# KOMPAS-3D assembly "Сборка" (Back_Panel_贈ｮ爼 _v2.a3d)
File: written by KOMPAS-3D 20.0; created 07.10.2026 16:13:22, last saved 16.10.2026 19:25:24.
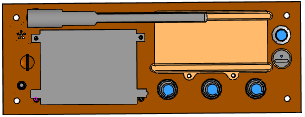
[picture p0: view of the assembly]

Document properties: Полное имя файла: D:\myProjects\Progect_esp32\box_compas\сборки компонентов\Back_Panel_Сборка_v2.a3d

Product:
- Part/product: Сборка
    Масса: 1.61309
  - Component [detail]: Деталь  | Масса: 0.0462657; source file: ..\корпус\крышка на монитор.m3d
  - Component [detail]: Деталь  | Масса: 0.0766137; source file: ..\корпус\крышка на батарейный отсек.m3d
  - Component [detail]: Деталь  | Масса: 0.0255021; source file: ..\корпус\п-стойка_2_l.m3d
  - Component [detail]: Деталь  | Масса: 0.0250596; source file: ..\корпус\п-стойка_2_r.m3d
  - Component [assembly]: Сборка  | qty 2  | Масса: 0.228921; source file: ILI9341_86_50_DevBoard.a3d
  - Component [assembly]: Сборка  | Масса: 0.0398888; source file: ..\переключатели и кнопки\KOQZM 2_3_4 asm.a3d
  - Component [assembly]: Сборка  | Масса: 0.0237077; source file: ..\переключатели и кнопки\button_momentary self-reset 12 asm.a3d
  - Component [assembly]: Сборка  | Масса: 0.0472654; source file: panel_ir_sd_jack_asm.a3d
  - Component [detail]: Деталь  | Материал: Фанера, береза,ФСФ ВВ/С ГОСТ 3916.1-2018 (density 760 kg/m3); Масса: 0.0227288; source file: ..\корпус\back_panel_v2.m3d
  - Component [detail]: Деталь  | Масса: 0.0197779; source file: ..\прочее\USB-C_Type-C.m3d
  - Component [assembly]: Сборка  | Масса: 0.119788; source file: ..\wifi\antenna wifi_asm.a3d
  - Component [assembly]: Сборка  | Масса: 0.425781; source file: ..\18650\my_ups_asm.a3d
  - Component [assembly]: Сборка  | qty 2  | Масса: 0.0186667; source file: ..\энкодер\TZT_EC11_asm.a3d
  - Component [assembly]: Сборка  | Масса: 0.245244; source file: ILI9341_81_50_DevBoard.a3d
  - Component [detail]: Деталь  | qty 2  | Масса: 0.000148431; source file: ..\прочее\Латунные рифленые гайки HUI JI.m3d

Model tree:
1. Эскиз:1  (with: Элемент выдавливания:1, Элемент выдавливания:2, Элемент выдавливания:5, Элемент выдавливания:26, Элемент выдавливания:3, Элемент выдавливания:29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)
     Расстояние = -15; Расстояние = 18.5; Расстояние = 0.5; Расстояние = 0.5

Referenced files in D:\myProjects\Progect_esp32\box_compas\сборки компонентов\: panel_ir_sd_jack_asm.a3d, ILI9341_86_50_DevBoard.a3d, ILI9341_81_50_DevBoard.a3d
Referenced files in D:\myProjects\Progect_esp32\box_compas\корпус\: back_panel_v2.m3d, п-стойка_2_r.m3d, п-стойка_2_l.m3d, крышка на батарейный отсек.m3d, крышка на монитор.m3d
Referenced files in D:\myProjects\Progect_esp32\box_compas\прочее\: USB-C_Type-C.m3d, Латунные рифленые гайки HUI JI.m3d
Referenced files in D:\myProjects\Progect_esp32\box_compas\wifi\: antenna wifi_asm.a3d
Referenced files in D:\myProjects\Progect_esp32\box_compas\18650\: my_ups_asm.a3d
Referenced files in D:\myProjects\Progect_esp32\box_compas\переключатели и кнопки\: button_momentary self-reset 12 asm.a3d, KOQZM 2_3_4 asm.a3d
Referenced files in D:\myProjects\Progect_esp32\box_compas\энкодер\: TZT_EC11_asm.a3d
Referenced files in D:\RicWork\Project-EPS32\box_compas\прочее\: Латунные рифленые гайки HUI JI.m3d
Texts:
  Сборка (1)
  Сборка (2)
  Деталь (1)
  Деталь (2)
